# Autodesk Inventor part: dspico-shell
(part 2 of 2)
feature "Combinar2"
  node "Sólido277"
  node "Sólido362"
  node "Sólido361"
  node "Sólido360"
  node "Sólido359"
  node "Sólido363"
  node "Sólido284"
  node "Sólido283"
  node "Sólido282"
  node "Sólido281"
  node "Sólido276"
  node "Sólido358"
  node "Sólido264"
  node "Sólido262"
  node "Sólido260"
  node "Sólido259"
  node "Sólido254"
  node "Sólido279"
  node "Sólido285"
  node "Sólido252"
  node "Sólido357"
  node "Sólido253"
  node "Sólido347"
  node "Sólido297"
  node "Sólido266"
  node "Sólido308"
  node "Sólido302"
  node "Sólido294"
  node "Sólido353"
  node "Sólido351"
  node "Sólido265"
  node "Sólido337"
  node "Sólido349"
  node "Sólido343"
  node "Sólido316"
  node "Sólido350"
  node "Sólido312"
  node "Sólido290"
  node "Sólido292"
  node "Sólido296"
  node "Sólido300"
  node "Sólido304"
  node "Sólido306"
  node "Sólido310"
  node "Sólido314"
  node "Sólido318"
  node "Sólido335"
  node "Sólido336"
  node "Sólido338"
  node "Sólido339"
  node "Sólido340"
  node "Sólido341"
  node "Sólido342"
  node "Sólido344"
  node "Sólido345"
  node "Sólido346"
  node "Sólido321"
  node "Sólido307"
  node "Sólido354"
  node "Sólido320"
  node "Sólido348"
  node "Sólido328"
  node "Sólido331"
  node "Sólido330"
  node "Sólido299"
  node "Sólido326"
  node "Sólido305"
  node "Sólido289"
  node "Sólido303"
  node "Sólido291"
  node "Sólido293"
  node "Sólido295"
  node "Sólido315"
  node "Sólido298"
  node "Sólido301"
  node "Sólido309"
  node "Sólido311"
  node "Sólido313"
  node "Sólido317"
  node "Sólido319"
  node "Sólido322"
  node "Sólido323"
  node "Sólido324"
  node "Sólido325"
  node "Sólido327"
  node "Sólido329"
  node "Sólido332"
  node "Sólido333"
  node "Sólido334"
  node "Sólido352"
  node "Sólido355"
  node "Sólido194"
  node "Sólido203"
  node "Sólido369"
  node "Sólido370"
  node "Sólido286"
  node "Sólido365"
  node "Sólido364"
  node "Sólido200"
  node "Sólido208"
  node "Sólido191"
  node "Sólido205"
  node "Sólido196"
  node "Sólido278"
  node "Sólido190"
  node "Sólido192"
  node "Sólido193"
  node "Sólido195"
  node "Sólido197"
  node "Sólido202"
  node "Sólido204"
  node "Sólido206"
  node "Sólido207"
  node "Sólido209"
  node "Sólido210"
  node "Sólido211"
  node "Sólido212"
  node "Sólido213"
  node "Sólido214"
  node "Sólido268"
  node "Sólido269"
  node "Sólido270"
  node "Sólido280"
  node "Sólido287"
  node "Sólido288"
  node "Sólido356"
  node "Sólido366"
  node "Sólido367"
  node "Sólido368"
  node "Sólido222"
  node "Sólido224"
  node "Sólido257"
  node "Sólido267"
  node "Sólido263"
  node "Sólido226"
  node "Sólido232"
  node "Sólido228"
  node "Sólido230"
  node "Sólido215"
  node "Sólido216"
  node "Sólido217"
  node "Sólido218"
  node "Sólido219"
  node "Sólido220"
  node "Sólido221"
  node "Sólido223"
  node "Sólido225"
  node "Sólido227"
  node "Sólido229"
  node "Sólido231"
  node "Sólido233"
  node "Sólido258"
  node "Sólido261"
  node "Sólido271"
  node "Sólido272"
  node "Sólido273"
  node "Sólido274"
  node "Sólido275"
  node "Sólido235"
  node "Sólido251"
  node "Sólido255"
  node "Sólido256"
  node "Sólido240"
  node "Sólido234"
  node "Sólido241"
  node "Sólido247"
  node "Sólido198"
  node "Sólido199"
  node "Sólido201"
  node "Sólido236"
  node "Sólido237"
  node "Sólido238"
  node "Sólido239"
  node "Sólido242"
  node "Sólido243"
  node "Sólido244"
  node "Sólido245"
  node "Sólido246"
  node "Sólido248"
  node "Sólido249"
  node "Sólido250"
feature "Desplazar cuerpo8"
feature "Desplazar cuerpo9"
feature "Desplazar cuerpo10"
feature "Desplazar cuerpo11"
feature "Desplazar cuerpo12"
sketch "Boceto44"
  geometry: L1 (-5.607, 17.586)-(4.393, 17.586); L2 (-11.107, 14.201)-(-11.107, 15.942) reference; L3 (-0.106, 15.942)-(-0.106, 3.121) reference; L4 (3.35, 17.5)-(-14.4, 17.5) reference; L5 (-11.107, 17.5)-(-0.106, 17.5); L6 (-11.107, 17.5)-(-11.107, 15.885); L7 (-0.106, 17.5)-(-0.106, 15.886); L8 (-0.231, 14.068)-(-0.231, 16.021) reference; L9 (-10.988, 15.885)-(-11.107, 15.885); L10 (-0.22, 15.886)-(-0.106, 15.886); L11 (-11.107, 17.5)-(-0.106, 17.5); A1 r 27.851 centre (-5.607, 43.211) between (-10.988, 15.885) and (-0.22, 15.886); 5 further points
  constraints: 14 end point, 2 horizontal, 2 point on circle, 2 point on line, 1 centre point, 1 collinear, 1 perpendicular
extrude "Extrusión33" cut sketch "Boceto44" distance "d224" = 1; taper "d225" = 0 deg
fillet "Empalme15" dims "d307" = 0.4
sketch "Boceto46"
  geometry: L1 (16.3, -12.5)-(16.3, 17.25) reference; L2 (16.05, 17.5)-(-15.3, 17.5) reference; C1 r 0.6 at (-13.211, -3.57) reference; C2 r 0.55 at (-13.21, -3.57); C3 r 0.6 at (13.21, -3.57) reference; C4 r 0.55 at (13.21, -3.57); C5 r 1 at (-15.3, 16.5); C6 r 0.55 at (-15.3, 16.5); C7 r 1 at (15.3, 16.5); C8 r 0.55 at (15.3, 16.5); A1 r 1 centre (-15.3, 16.5) between (-15.3, 17.5) and (-16.3, 16.5) reference; 1 further point
  constraints: 6 centre point, 5 coincident
  dimensions: "d313" = 1.1 diameter of C2; "d314" = 1.1 diameter of C4; "d324" = 2 diameter of C5; "d325" = 1.1 diameter of C6; "d329" = 2 diameter of C7; "d330" = 1.1 diameter of C8; "d332" = 1 distance from line of L1 C7.centre; "d333" = 1 distance from line of L2 C7.centre
extrude "Extrusión34" join sketch "Boceto46" distance "d315" = 1.2; taper "d316" = 0 deg
fillet "Empalme16" dims "d317" = 0.2
sketch "Boceto47"
  geometry: L1 (1.854, 1.85)-(1.854, 0) reference; L2 (1.854, 1.85)-(0.354, 1.85); L3 (0.354, 1.85)-(0.354, 0.85) reference; L4 (0.354, 1.85)-(0.354, 0.85); L5 (0.354, 0.85)-(0, 0.85) reference; L6 (0.354, 0.85)-(0, 0.85); L7 (0, 0.85)-(0, 0); L8 (0, 0)-(1.854, 0); L9 (1.854, 0)-(1.854, 1.85); 2 further points
  constraints: 12 end point, 5 perpendicular, 1 horizontal
extrude "Extrusión35" join sketch "Boceto47" distance "d334" = 0.4; taper "d335" = 0 deg
fillet "Empalme17" dims "d336" = 0.25
sketch "Boceto48"
  geometry: L1 (1.273, 1.899)-(1.273, 7.939); L2 (1.273, 7.939)-(2.681, 7.939); L3 (2.681, 7.939)-(2.681, 1.899); L4 (2.681, 1.899)-(1.273, 1.899); 1 further point
  constraints: 2 other
extrude "Extrusión36" join sketch "Boceto48" distance "d337" = 0.3; taper "d338" = 0 deg
sketch "Boceto49"
  geometry: L1 (32.35, -1)-(32.35, -31.9) reference; L2 (2.75, -1)-(29.35, -1) reference; L3 (0, 0)-(31.35, 0) reference; L4 (29.25, 0)-(29.25, -3.1); L5 (28.75, -3.6)-(15.55, -3.6); L6 (15.05, -3.1)-(15.05, 0); L7 (15.05, 0)-(29.25, 0); A1 r 0.5 centre (15.55, -3.1) between (15.05, -3.1) and (15.55, -3.6); A2 r 0.5 centre (28.75, -3.1) between (28.75, -3.6) and (29.25, -3.1); 4 further points
  constraints: 8 end point, 5 point on line, 4 point on circle, 4 tangent, 2 centre point, 2 perpendicular, 1 equal radius, 1 horizontal
  dimensions: "d340" = 3.6 distance of L4.start point (29.25, -3.6); "d341" = 14.2 distance of point (29.25, -3.6) point (15.05, -3.6); "d342" = 3.1 distance between parallel lines of L1 L4; "d343" = 0.5 radius of A1
extrude "DEV-PORT" cut sketch "Boceto49" distance "d344" = 0.8; taper "d345" = 0 deg
sketch "Boceto50"
  geometry: L1 (15.065, -14.3)-(15.065, -4.357); L2 (15.065, -4.357)-(18.22, -4.357); L3 (18.22, -4.357)-(18.22, -14.3); L4 (18.22, -14.3)-(15.065, -14.3); 1 further point
  constraints: 2 other
extrude "Text-PINOUT" cut sketch "Boceto50" distance "d346" = 0.2; taper "d347" = 0 deg
sketch "Boceto51"
  geometry: L1 (-8.354, -8.2)-(-7.454, -8.2) reference; L2 (-4.454, -17.5)-(-5.354, -17.5) reference; L3 (-7.904, -8.2)-(-4.904, -8.2); L4 (-4.904, -8.2)-(-4.904, -17.5); L5 (-4.904, -17.5)-(-7.904, -17.5); L6 (-7.904, -17.5)-(-7.904, -8.2); L7 (-1.907, -8.2)-(1.192, -8.2); L8 (1.192, -8.2)-(1.192, -17.5); L9 (1.192, -17.5)-(-1.907, -17.5); L10 (-1.907, -17.5)-(-1.907, -8.2); L11 (3.646, -8.2)-(4.546, -8.2) reference; L12 (4.096, -8.2)-(7.224, -8.2); L13 (7.224, -8.2)-(7.224, -17.5); L14 (7.224, -17.5)-(4.096, -17.5); L15 (4.096, -17.5)-(4.096, -8.2); 4 further points
  constraints: 24 end point, 6 parallel, 3 horizontal, 3 midpoint, 3 perpendicular, 2 point on line
extrude "Delete_rails" cut sketch "Boceto51" distance "d348" = 2.55; taper "d349" = 0 deg
sketch "Boceto29"
  geometry: 1 further point
fillet "Empalme12" dims "d120" = 0.5
feature "ֹ耀ֻ耀ֽ耀ֿ耀ׁ耀׃耀ׅ耀ׇ耀" dims "d0" = 32.6, "d1" = 35, "d2" = 3.85, "d3" = 0, "d4" = 2.85, "d5" = 3, "d6" = 1.95, "d7" = 18.3, "d8" = 5, "d9" = 0, "d10" = 0, "d11" = 1.76, "d12" = 6.1, "d13" = 1.76, "d14" = 1, "d15" = 7, "d16" = 0.9, "d17" = 1, "d18" = 0, "d19" = 2.15, "d20" = 0, "d21" = 2, "d22" = 0, "d23" = 5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
feature "ف耀ك耀م耀ه耀ى耀ً耀ٍ耀ُ耀" dims "d0" = 32.6, "d1" = 35, "d2" = 3.85, "d3" = 0, "d4" = 2.85, "d5" = 3, "d6" = 1.95, "d7" = 18.3, "d8" = 5, "d9" = 0, "d10" = 0, "d11" = 1.76, "d12" = 6.1, "d13" = 1.76, "d14" = 1, "d15" = 7, "d16" = 0.9, "d17" = 1, "d18" = 0, "d19" = 2.15, "d20" = 0, "d21" = 2, "d22" = 0, "d23" = 5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
node "Bottom"
node "Contorno proyectado1"
node "Contorno proyectado3"
node "Contorno proyectado4"
node "Contorno proyectado5"
node "Contorno proyectado6"
node "Contorno proyectado7"
node "Contorno proyectado8"
node "Contorno proyectado11"
node "Contorno proyectado12"
node "Contorno proyectado13"
node "Contorno proyectado14"
node "Contorno proyectado15"
node "Contorno proyectado16"
node "Contorno proyectado17"
node "Contorno proyectado18"
node "Contorno proyectado20"
node "Contorno proyectado22"
node "Contorno proyectado23"
node "Contorno proyectado24"
node "Contorno proyectado25"
node "Contorno proyectado26"
node "Top"
node "DSpico"
node "Sólido4"
node "Sólido5"
node "Sólido6"
node "Sólido7"
node "Sólido8"
node "Sólido9"
node "Sólido10"
node "Sólido11"
node "Sólido12"
node "Sólido13"
node "Sólido14"
node "Sólido15"
node "Sólido16"
node "Sólido17"
node "Sólido18"
node "Sólido19"
node "Sólido20"
node "Sólido21"
node "Sólido22"
node "Sólido23"
node "Sólido24"
node "Sólido25"
node "Sólido26"
node "Sólido27"
node "Sólido28"
node "Sólido29"
node "Sólido30"
node "Sólido31"
node "Sólido32"
node "Sólido33"
node "Sólido34"
node "Sólido35"
node "Sólido36"
node "Sólido37"
node "Sólido38"
node "Sólido39"
node "Sólido40"
node "Sólido41"
node "Sólido42"
node "Sólido43"
node "Sólido44"
node "Sólido45"
node "Sólido46"
node "Sólido47"
node "Sólido48"
node "Sólido49"
node "Sólido50"
node "Sólido51"
node "Sólido52"
node "Sólido53"
node "Sólido54"
node "Sólido55"
node "Sólido56"
node "Sólido57"
node "Sólido58"
node "Sólido59"
node "Sólido60"
node "Sólido61"
node "Sólido62"
node "Sólido63"
node "Sólido64"
node "Sólido65"
node "Sólido66"
node "Sólido67"
node "Sólido68"
node "Sólido69"
node "Sólido70"
node "Sólido71"
node "Sólido72"
node "Sólido73"
node "Sólido74"
node "Sólido75"
node "Sólido76"
node "Sólido77"
node "Sólido78"
node "Sólido79"
node "Sólido80"
node "Sólido81"
node "Sólido82"
node "Sólido83"
node "Sólido84"
node "Sólido85"
node "Sólido86"
node "Sólido87"
node "Sólido88"
node "Sólido89"
node "Sólido90"
node "Sólido91"
node "Sólido92"
node "Sólido93"
node "Sólido94"
node "Sólido95"
node "Sólido96"
node "Sólido97"
node "Sólido98"
node "Sólido99"
node "Sólido100"
node "Sólido101"
node "Sólido102"
node "Sólido103"
node "Sólido104"
node "Sólido105"
node "Sólido106"
node "Sólido107"
node "Sólido108"
node "Sólido109"
node "Sólido110"
node "Sólido111"
node "Sólido112"
node "Sólido113"
node "Sólido114"
node "Sólido115"
node "Sólido116"
node "Sólido117"
node "Sólido118"
node "Sólido119"
node "Sólido120"
node "Sólido121"
node "Sólido122"
node "Sólido123"
node "Sólido124"
node "Sólido125"
node "Sólido126"
node "Sólido127"
node "Sólido128"
node "Sólido129"
node "Sólido130"
node "Sólido131"
node "Sólido132"
node "Sólido133"
node "Sólido134"
node "Sólido135"
node "Sólido136"
node "Sólido137"
node "Sólido138"
node "Sólido139"
node "Sólido140"
node "Sólido141"
node "Sólido142"
node "Sólido143"
node "Sólido144"
node "Sólido145"
node "Sólido146"
node "Sólido147"
node "Sólido148"
node "Sólido149"
node "Sólido150"
node "Sólido151"
node "Sólido152"
node "Sólido153"
node "Sólido154"
node "Sólido155"
node "Sólido156"
node "Sólido157"
node "Sólido158"
node "Sólido159"
node "Sólido160"
node "Sólido161"
node "Sólido162"
node "Sólido163"
node "Sólido164"
node "Sólido165"
node "Sólido166"
node "Sólido167"
node "Sólido168"
node "Sólido169"
node "Sólido170"
node "Sólido171"
node "Sólido172"
node "Sólido173"
node "Sólido174"
node "Sólido175"
node "Sólido176"
node "Sólido177"
node "Sólido178"
node "Sólido179"
node "Sólido180"
node "Sólido181"
node "Sólido182"
node "Sólido183"
node "Sólido184"
node "Sólido185"
node "DSPICO 2"
